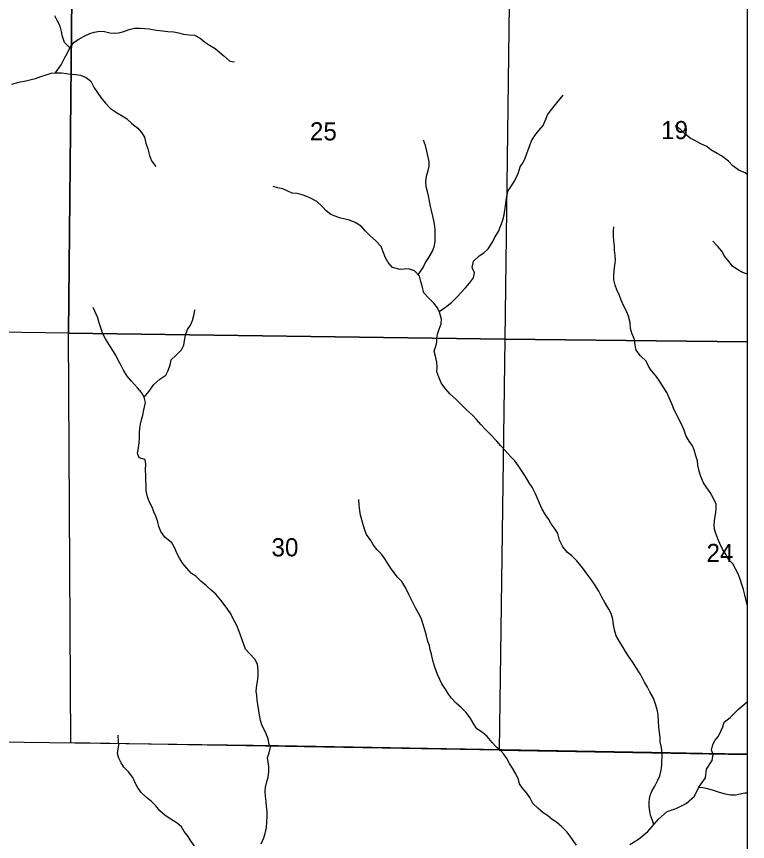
# Model space of a CAD drawing. Extents: x -10 to 158, y 8 to 33.
# Drawn here: x 7.212 to 8.9, y 16.648 to 18.554 of the extents above; entities that cross this region are included whole.
import ezdxf

# ---------------------------------------------------------------- set-up
doc = ezdxf.new("R2010")
doc.units = 0
for name, color, linetype in [('GM_X_Corporation', 7, 'Continuous'), ('GM_X_Minor_River', 7, 'Continuous'), ('GM_X_Section_Text', 7, 'Continuous')]:
    doc.layers.add(name, color=color, linetype=linetype)

msp = doc.modelspace()

# ---------------------------------------------------------------- linework, layer by layer
at = {"layer": 'GM_X_Corporation'}
for points in [[(7.3418, 18.8315), (7.332, 17.8222), (6.4651, 17.8343), (6.4692, 18.3911), (6.4726, 18.8258)], [(8.353, 18.8213), (8.3394, 17.8082), (7.332, 17.8222), (7.3418, 18.8315)], [(8.9, 17.8023), (8.9, 18.8136), (8.353, 18.8213), (8.3394, 17.8082)], [(8.3394, 17.8082), (8.3265, 16.8592), (7.3376, 16.8759), (7.332, 17.8222)], [(8.9, 16.8494), (8.9, 17.8023), (8.3394, 17.8082), (8.3265, 16.8592)]]:
    msp.add_lwpolyline(points, close=True, dxfattribs=at)
msp.add_lwpolyline([(2.1, 14.1), (8.9, 14.1), (8.9, 16.8499), (8.7964, 16.8517), (8.7214, 16.8529), (7.8171, 16.8692), (6.5825, 16.8858), (6.4571, 16.891), (6.4525, 17.3965), (6.1753, 17.3961), (5.7441, 17.4016), (5.3204, 17.3974)], dxfattribs=at)
at = {"layer": 'GM_X_Minor_River'}
for points in [[(7.3352, 18.4812), (7.323, 18.4937), (7.3186, 18.5077), (7.3162, 18.5191), (7.313, 18.5308), (7.3049, 18.5455), (7.3002, 18.5553)], [(7.3019, 18.4236), (7.3149, 18.442), (7.3227, 18.4573), (7.3297, 18.4699), (7.336, 18.4829), (7.3454, 18.4944), (7.3563, 18.5014), (7.3668, 18.5072), (7.3811, 18.5139), (7.391, 18.5174), (7.4046, 18.5195), (7.4152, 18.5185), (7.4274, 18.516), (7.4373, 18.515), (7.4475, 18.5155), (7.4596, 18.5191), (7.4725, 18.5234), (7.4842, 18.5262), (7.4978, 18.5268), (7.5085, 18.5261), (7.518, 18.5251), (7.5343, 18.5223), (7.5491, 18.5206), (7.5617, 18.5192), (7.5753, 18.5183), (7.5864, 18.5158), (7.5978, 18.5125), (7.6107, 18.5108), (7.6229, 18.5102), (7.6362, 18.5035), (7.6458, 18.4953), (7.6573, 18.4871), (7.6707, 18.4793), (7.6811, 18.4714), (7.6907, 18.4628), (7.7049, 18.4505), (7.7151, 18.4487)], [(7.2013, 18.3976), (7.2172, 18.4016), (7.2339, 18.4049), (7.246, 18.4077), (7.2558, 18.4105), (7.2682, 18.4148), (7.2781, 18.418), (7.2917, 18.4223), (7.3019, 18.4236), (7.3156, 18.4238), (7.3277, 18.4217), (7.3372, 18.4206), (7.349, 18.4197), (7.3596, 18.4183), (7.373, 18.4128), (7.3834, 18.4038), (7.3915, 18.3891), (7.3981, 18.3785), (7.407, 18.3661), (7.4174, 18.3537), (7.4293, 18.341), (7.4427, 18.332), (7.4557, 18.3242), (7.4657, 18.3179), (7.4787, 18.3063), (7.4921, 18.2954), (7.501, 18.2857), (7.5076, 18.2751), (7.5104, 18.2611), (7.5152, 18.2479), (7.5195, 18.2328), (7.5235, 18.2199), (7.5339, 18.2075)], [(8.1884, 17.8722), (8.2029, 17.8824), (8.2164, 17.8932), (8.2299, 17.9063), (8.2385, 17.9159), (8.2486, 17.927), (8.2579, 17.9374), (8.2676, 17.95), (8.2694, 17.9615), (8.2639, 17.9739), (8.2671, 17.9884), (8.2806, 18.0011), (8.2908, 18.0081), (8.3013, 18.0173), (8.3113, 18.0322), (8.3161, 18.0426), (8.325, 18.0571), (8.3302, 18.0708), (8.3342, 18.0811), (8.3378, 18.0956), (8.3396, 18.1063), (8.341, 18.1158), (8.3427, 18.1287), (8.3441, 18.1386), (8.3477, 18.1508), (8.3552, 18.1623), (8.3611, 18.1722), (8.3663, 18.1826), (8.3711, 18.1936), (8.3754, 18.2066), (8.3821, 18.2166), (8.3866, 18.2261), (8.391, 18.2391), (8.395, 18.2494), (8.4016, 18.2665), (8.409, 18.2784), (8.418, 18.2899), (8.4281, 18.3018), (8.4343, 18.3163), (8.4384, 18.3262), (8.4451, 18.3358), (8.4533, 18.3466), (8.4634, 18.3585), (8.4746, 18.3719)], [(8.9, 18.188), (8.8943, 18.1927), (8.8806, 18.1979), (8.8664, 18.2087), (8.856, 18.2192), (8.8403, 18.2315), (8.83, 18.2371), (8.8154, 18.2456), (8.8059, 18.2531), (8.7921, 18.2598), (8.7784, 18.2672), (8.7677, 18.2727), (8.7546, 18.2836), (8.7446, 18.2933), (8.7328, 18.3012)], [(8.1394, 17.9573), (8.1508, 17.974), (8.1568, 17.9858), (8.1638, 17.9973), (8.1727, 18.0119), (8.1768, 18.0214), (8.1785, 18.0343), (8.1787, 18.0484), (8.1786, 18.0602), (8.178, 18.0696), (8.176, 18.0825), (8.1732, 18.0924), (8.1708, 18.1026), (8.168, 18.1151), (8.1659, 18.1268), (8.1635, 18.1393), (8.1607, 18.1492), (8.1583, 18.1601), (8.1574, 18.1715), (8.1591, 18.1848), (8.1627, 18.1978), (8.1648, 18.2081), (8.1647, 18.2187), (8.1623, 18.2289), (8.1595, 18.2422), (8.1563, 18.2554), (8.1519, 18.2679)], [(8.0419, 18.0356), (8.0289, 18.0472), (8.0181, 18.0581), (8.0077, 18.069), (7.9943, 18.0779), (7.981, 18.083), (7.9711, 18.0856), (7.9581, 18.0888), (7.9475, 18.0921), (7.9379, 18.0965), (7.9272, 18.1048), (7.9179, 18.1149), (7.9056, 18.1265), (7.8923, 18.1335), (7.8824, 18.1376), (7.8717, 18.1416), (7.8595, 18.1449), (7.8485, 18.1455), (7.8386, 18.1499), (7.8271, 18.1555), (7.8146, 18.158), (7.805, 18.1613)], [(8.9, 17.1913), (8.8998, 17.1919), (8.8962, 17.2081), (8.8938, 17.2184), (8.8906, 17.2305), (8.887, 17.2422), (8.8827, 17.2539), (8.8784, 17.2664), (8.8663, 17.2898), (8.8563, 17.2999), (8.8509, 17.3105), (8.8431, 17.3218), (8.8361, 17.3369), (8.8318, 17.3471), (8.8267, 17.3595), (8.8235, 17.3697), (8.823, 17.3807), (8.8247, 17.3948), (8.8272, 17.4078), (8.8278, 17.4176), (8.8273, 17.4271), (8.8215, 17.4407), (8.8137, 17.4547), (8.806, 17.4648), (8.7982, 17.4769), (8.7923, 17.4912), (8.7884, 17.5033), (8.7855, 17.5173), (8.7847, 17.5272), (8.7807, 17.5389), (8.7771, 17.5525), (8.7732, 17.5624), (8.7651, 17.5729), (8.7577, 17.5857), (8.7549, 17.5963), (8.7494, 17.6088), (8.737, 17.6329), (8.7288, 17.6491), (8.7249, 17.6593), (8.719, 17.6726), (8.7135, 17.6854), (8.7054, 17.6986), (8.6957, 17.7129), (8.6891, 17.7231), (8.6783, 17.7354), (8.6717, 17.746), (8.6659, 17.7577), (8.6532, 17.7697), (8.6432, 17.7828), (8.6404, 17.7946), (8.6391, 17.8078), (8.6328, 17.8222), (8.63, 17.8332), (8.6287, 17.8468), (8.6251, 17.8616), (8.6212, 17.8718), (8.6145, 17.8846), (8.6083, 17.8986), (8.6043, 17.9092), (8.5985, 17.9224), (8.5942, 17.933), (8.5917, 17.9458), (8.5912, 17.9568), (8.5922, 17.9671), (8.5939, 17.9789), (8.5953, 17.9907), (8.5944, 18.0013), (8.5931, 18.0142), (8.5926, 18.0237), (8.5917, 18.0347), (8.5908, 18.0468), (8.5902, 18.0582), (8.5913, 18.0681)], [(8.7026, 16.852), (8.7011, 16.8654), (8.6987, 16.8787), (8.6982, 16.8882), (8.6969, 16.9007), (8.6952, 16.9124), (8.6946, 16.9265), (8.6937, 16.9397), (8.6924, 16.95), (8.6885, 16.9636), (8.6833, 16.9795), (8.6748, 16.9942), (8.6693, 17.0051), (8.6624, 17.016), (8.6573, 17.0259), (8.6507, 17.0379), (8.6437, 17.0488), (8.6348, 17.0632), (8.6271, 17.0741), (8.6186, 17.0869), (8.6131, 17.0967), (8.6042, 17.1106), (8.5968, 17.1234), (8.5937, 17.134), (8.5904, 17.1484), (8.5891, 17.1621), (8.5851, 17.1753), (8.5801, 17.1851), (8.5708, 17.2002), (8.5638, 17.213), (8.5564, 17.2262), (8.5475, 17.2413), (8.5393, 17.2533), (8.5278, 17.2687), (8.5197, 17.2796), (8.5058, 17.2962), (8.4946, 17.3082), (8.4843, 17.3156), (8.4739, 17.3288), (8.4661, 17.3443), (8.4617, 17.3598), (8.4559, 17.3696), (8.447, 17.382), (8.4412, 17.3922), (8.4334, 17.4031), (8.4257, 17.4155), (8.4198, 17.4295), (8.4151, 17.4404), (8.4104, 17.451), (8.4026, 17.4669), (8.396, 17.477), (8.3871, 17.4914), (8.3794, 17.503), (8.3705, 17.5166), (8.3627, 17.5271), (8.3527, 17.5376), (8.34, 17.5523), (8.3304, 17.5624), (8.3215, 17.5729), (8.3077, 17.5875), (8.2942, 17.6007), (8.2846, 17.6115), (8.2746, 17.6232), (8.265, 17.6333), (8.2515, 17.6449), (8.2396, 17.6569), (8.2266, 17.6697), (8.2135, 17.6813), (8.2035, 17.6929), (8.1931, 17.7064), (8.1872, 17.7204), (8.1825, 17.7329), (8.1835, 17.7439), (8.1826, 17.7553), (8.1793, 17.7689), (8.1765, 17.7807), (8.1798, 17.7902), (8.1823, 17.8009), (8.183, 17.8104), (8.1844, 17.8199), (8.1884, 17.8317), (8.1924, 17.8439), (8.1934, 17.8549), (8.189, 17.8708), (8.1843, 17.881), (8.1758, 17.8919), (8.1635, 17.9035), (8.1524, 17.9155), (8.1488, 17.9307), (8.146, 17.9413), (8.1424, 17.9541), (8.1308, 17.9665), (8.1175, 17.9709), (8.1073, 17.97), (8.0978, 17.9695), (8.0803, 17.9738), (8.0699, 17.9858), (8.0644, 17.9964), (8.0586, 18.0104), (8.0538, 18.0221), (8.0419, 18.0356)], [(8.9, 17.9585), (8.8882, 17.9622), (8.8752, 17.97), (8.8656, 17.9771), (8.8579, 17.9868), (8.8467, 18), (8.8405, 18.0117), (8.8316, 18.0226), (8.8201, 18.035)], [(7.7986, 16.8663), (7.7958, 16.8724), (7.7929, 16.8853), (7.7867, 16.9007), (7.7793, 16.9158), (7.7757, 16.9276), (7.7733, 16.9401), (7.7716, 16.9503), (7.7703, 16.9605), (7.7679, 16.9745), (7.7666, 16.9855), (7.7653, 16.9958), (7.767, 17.0091), (7.7691, 17.0228), (7.7701, 17.0334), (7.7704, 17.0437), (7.7687, 17.0581), (7.7621, 17.0698), (7.7498, 17.0829), (7.7409, 17.0927), (7.7362, 17.1055), (7.7259, 17.1335), (7.7205, 17.1471), (7.7134, 17.1611), (7.7068, 17.1743), (7.7002, 17.184), (7.6917, 17.1957), (7.684, 17.2055), (7.6721, 17.2194), (7.6613, 17.2287), (7.6506, 17.2392), (7.6375, 17.2493), (7.6264, 17.2609), (7.6164, 17.2676), (7.6053, 17.2796), (7.5964, 17.2905), (7.5887, 17.3026), (7.5832, 17.3128), (7.577, 17.3271), (7.5707, 17.3381), (7.5546, 17.3511), (7.5454, 17.3643), (7.541, 17.376), (7.5382, 17.3866), (7.5335, 17.3999), (7.5288, 17.4097), (7.5253, 17.4206), (7.5194, 17.4319), (7.5147, 17.444), (7.5111, 17.4584), (7.5113, 17.4717), (7.5108, 17.4827), (7.5103, 17.493), (7.5101, 17.5066), (7.5107, 17.5196), (7.509, 17.5309), (7.4953, 17.5345), (7.4918, 17.5455), (7.4935, 17.5569), (7.4952, 17.5695), (7.4958, 17.5805), (7.4961, 17.5919), (7.4971, 17.6029), (7.4985, 17.6124), (7.5006, 17.6219), (7.5039, 17.6326), (7.5064, 17.6452), (7.5096, 17.6623), (7.5071, 17.6744), (7.5009, 17.6854), (7.4917, 17.6963), (7.4778, 17.7113), (7.4674, 17.7233), (7.4589, 17.7365), (7.4542, 17.7463), (7.4464, 17.7602), (7.4414, 17.7715), (7.4328, 17.7847), (7.4266, 17.7945), (7.4177, 17.8092), (7.4115, 17.8209), (7.4064, 17.8349), (7.4032, 17.8459), (7.3996, 17.858), (7.3887, 17.8817)], [(7.5072, 17.6741), (7.5183, 17.6882), (7.5291, 17.704), (7.543, 17.7159), (7.5569, 17.7252), (7.5625, 17.7363), (7.5669, 17.7489), (7.5694, 17.7607), (7.5806, 17.7718), (7.5933, 17.7838), (7.5981, 17.7948), (7.6003, 17.8055), (7.6024, 17.8177), (7.6071, 17.8306), (7.6135, 17.841), (7.6182, 17.8517), (7.6222, 17.8662), (7.6236, 17.876)], [(8.3307, 16.8579), (8.3213, 16.8658), (8.3106, 16.8771), (8.299, 16.8906), (8.2879, 16.9), (8.2749, 16.9089), (8.2679, 16.9191), (8.2597, 16.9342), (8.2493, 16.9473), (8.2397, 16.9571), (8.227, 16.9679), (8.2163, 16.9792), (8.2097, 16.989), (8.2027, 16.9999), (8.1942, 17.0123), (8.1895, 17.0229), (8.1844, 17.0338), (8.1781, 17.0508), (8.1734, 17.0663), (8.1705, 17.0811), (8.167, 17.0909), (8.1654, 17.1008), (8.1622, 17.1106), (8.1586, 17.1235), (8.1546, 17.1375), (8.1511, 17.1496), (8.1467, 17.164), (8.1409, 17.1745), (8.1335, 17.1881), (8.1253, 17.2032), (8.1179, 17.2187), (8.1109, 17.2338), (8.1016, 17.2485), (8.0919, 17.259), (8.0796, 17.2748), (8.0699, 17.2891), (8.0629, 17.3011), (8.056, 17.3113), (8.0452, 17.3222), (8.0367, 17.3331), (8.0305, 17.3432), (8.0205, 17.3572), (8.0165, 17.3674), (8.0134, 17.3772), (8.0094, 17.3912), (8.0066, 17.4022), (8.0049, 17.4128), (8.0033, 17.4253), (8.0027, 17.4382)], [(8.8206, 16.8501), (8.8166, 16.8597), (8.8202, 16.8726), (8.8257, 16.8822), (8.8328, 16.8918), (8.8384, 16.9032), (8.8428, 16.9135), (8.8464, 16.9238), (8.8596, 16.935), (8.8791, 16.9543), (8.8937, 16.9666), (8.9, 16.9719)], [(7.4483, 16.8719), (7.4474, 16.88), (7.4468, 16.8937)], [(7.6232, 16.6385), (7.6156, 16.6487), (7.6081, 16.6597), (7.5995, 16.6719), (7.5927, 16.6821), (7.5828, 16.6905), (7.5683, 16.6999), (7.555, 16.7084), (7.5433, 16.7196), (7.5335, 16.731), (7.5237, 16.7406), (7.5123, 16.7502), (7.5002, 16.7614), (7.4916, 16.7739), (7.4859, 16.7841), (7.4807, 16.7965), (7.4706, 16.8094), (7.4601, 16.8202), (7.4536, 16.83), (7.4484, 16.8412), (7.4454, 16.8516), (7.4468, 16.8619), (7.4483, 16.8719)], [(7.7771, 16.6429), (7.783, 16.6571), (7.7861, 16.6669), (7.7894, 16.6808), (7.7903, 16.6933), (7.7909, 16.707), (7.7906, 16.7177), (7.7895, 16.7295), (7.7885, 16.7406), (7.7871, 16.7532), (7.7864, 16.7639), (7.7872, 16.7737), (7.7896, 16.7839), (7.7932, 16.7971), (7.7949, 16.8099), (7.795, 16.8213), (7.7935, 16.8324), (7.7917, 16.8424), (7.7955, 16.8533), (7.7986, 16.8663)], [(8.5049, 16.6396), (8.4974, 16.651), (8.4906, 16.6608), (8.4826, 16.6707), (8.471, 16.6826), (8.4592, 16.6934), (8.4492, 16.6995), (8.4378, 16.7084), (8.4282, 16.7149), (8.4157, 16.7253), (8.4044, 16.7364), (8.3973, 16.7497), (8.3905, 16.7599), (8.3804, 16.7713), (8.3739, 16.7815), (8.3713, 16.7919), (8.365, 16.8047), (8.3572, 16.818), (8.3508, 16.8285), (8.3441, 16.8402), (8.3373, 16.8504), (8.3307, 16.8579)], [(8.6283, 16.6413), (8.648, 16.6542), (8.6699, 16.6716), (8.6945, 16.7001), (8.7142, 16.7179), (8.7353, 16.7248), (8.7584, 16.7361), (8.7777, 16.7528), (8.7875, 16.7737), (8.8034, 16.7954), (8.8057, 16.8155), (8.8186, 16.8356), (8.8206, 16.8501)], [(8.6839, 16.6874), (8.6805, 16.6971), (8.676, 16.7091), (8.6742, 16.7187), (8.6727, 16.729), (8.6728, 16.7397), (8.6748, 16.7525), (8.6792, 16.7645), (8.6857, 16.776), (8.6923, 16.7883), (8.6974, 16.7999), (8.7006, 16.813), (8.7023, 16.8251), (8.7026, 16.852)], [(8.788, 16.7741), (8.7967, 16.7731), (8.8073, 16.7711), (8.8204, 16.7671), (8.8347, 16.7627), (8.8486, 16.7583), (8.8607, 16.7563), (8.8725, 16.7561), (8.8833, 16.7587), (8.894, 16.7605), (8.9, 16.7612)]]:
    msp.add_lwpolyline(points, dxfattribs=at)

# ---------------------------------------------------------------- texts
at = {"layer": 'GM_X_Section_Text'}
for s, p in [('25', (7.8895, 18.2674)), ('19', (8.7004, 18.2703)), ('30', (7.8008, 17.3069)), ('24', (8.8053, 17.2939))]:
    msp.add_text(s, height=0.04186, rotation=0, dxfattribs=at).set_placement(p)

doc.saveas('drawing.dxf')
